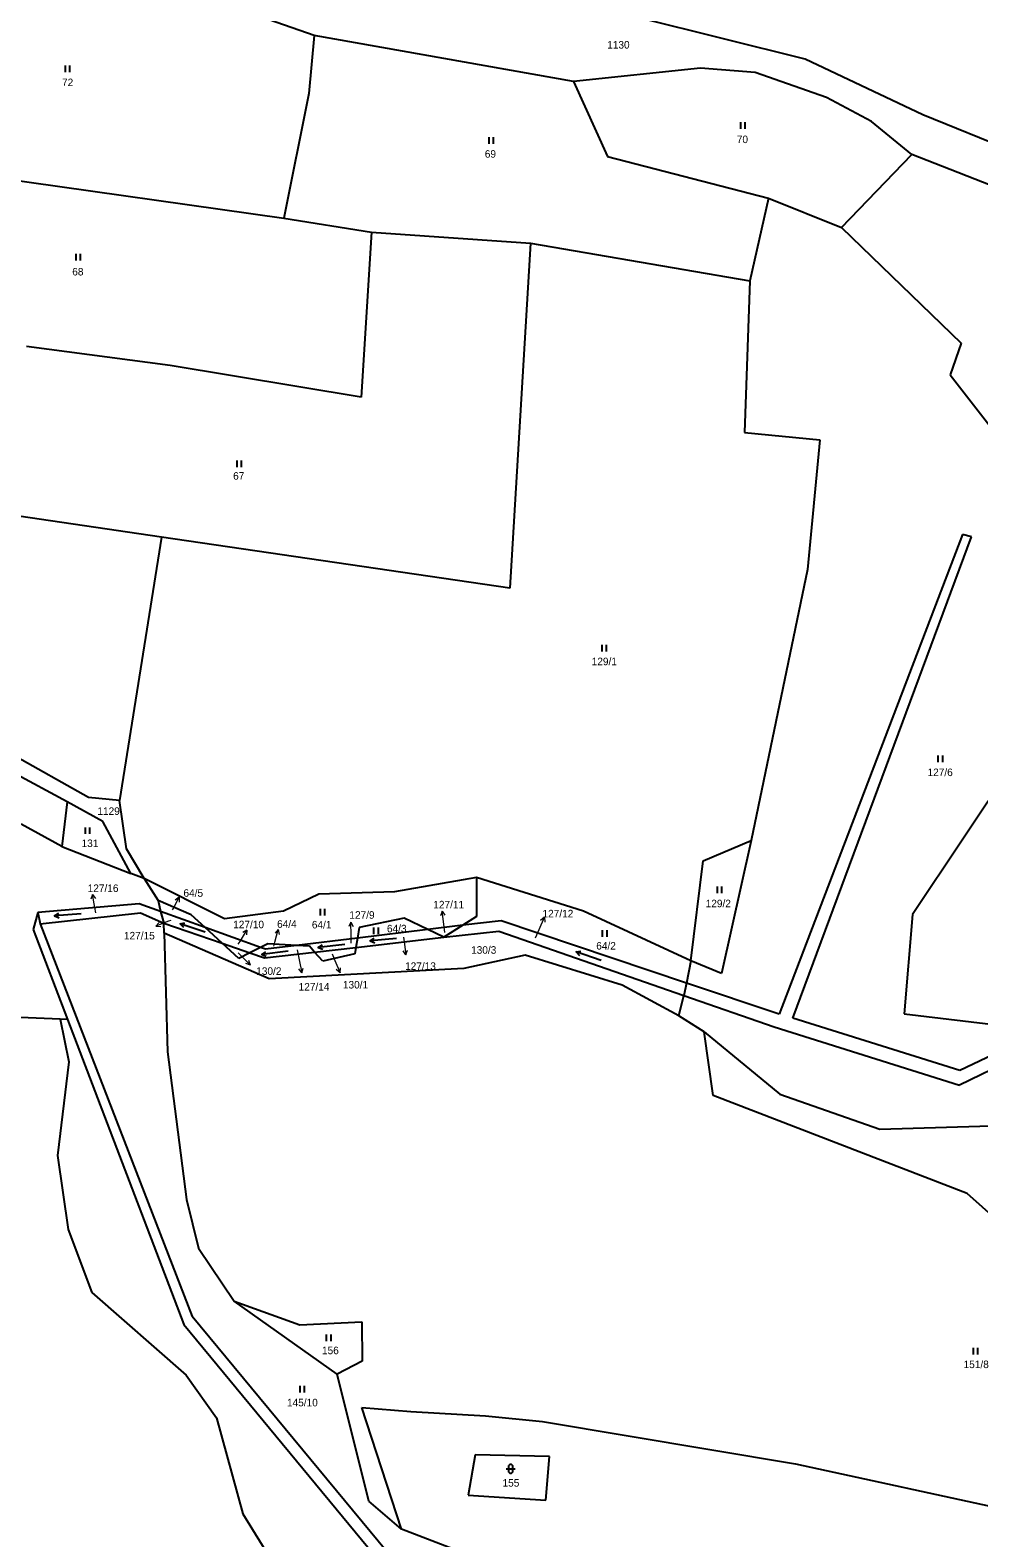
# Model space of a CAD drawing. Extents: x -765428 to -762163, y -1107632 to -1104975.
# Drawn here: x -763790.9 to -763576.9, y -1106368.4 to -1106028 of the extents above; entities that cross this region are included whole.
import ezdxf
from ezdxf.enums import TextEntityAlignment as Align

# ---------------------------------------------------------------- set-up
doc = ezdxf.new("R2010")
doc.units = 0
doc.header["$LTSCALE"] = 0.68
for name, color, linetype, lineweight in [('1', 7, 'Continuous', 25), ('3', 7, 'Continuous', 25), ('7', 7, 'Continuous', 13)]:
    doc.layers.add(name, color=color, linetype=linetype, lineweight=lineweight)
doc.layers.add('2', color=7, linetype='Continuous')

msp = doc.modelspace()

# ---------------------------------------------------------------- linework, layer by layer
at = {"layer": '1'}
for p, q in [((-763726.87, -1106029.18), (-763753.11, -1106020.03)), ((-763616.09, -1106034.57), (-763653.49, -1106025.2)), ((-763726.87, -1106029.18), (-763728.05, -1106042.27)), ((-763668.33, -1106039.62), (-763726.87, -1106029.18)), ((-763589.52, -1106047.15), (-763616.09, -1106034.57)), ((-763639.64, -1106036.55), (-763668.33, -1106039.62)), ((-763627.35, -1106037.56), (-763639.64, -1106036.55)), ((-763728.05, -1106042.27), (-763733.72, -1106070.47)), ((-763668.33, -1106039.62), (-763660.67, -1106056.49)), ((-763591.96, -1106056.09), (-763601.08, -1106048.6)), ((-763545.6, -1106064.87), (-763589.52, -1106047.15)), ((-763834.64, -1106056.18), (-763733.72, -1106070.47)), ((-763660.67, -1106056.49), (-763624.36, -1106065.9)), ((-763607.85, -1106072.56), (-763591.96, -1106056.09)), ((-763549.32, -1106072.75), (-763591.96, -1106056.09)), ((-763624.36, -1106065.9), (-763628.51, -1106084.61)), ((-763624.36, -1106065.9), (-763607.85, -1106072.56)), ((-763733.72, -1106070.47), (-763713.95, -1106073.6)), ((-763607.85, -1106072.56), (-763580.88, -1106098.69)), ((-763713.95, -1106073.6), (-763716.25, -1106110.83)), ((-763713.95, -1106073.6), (-763678.06, -1106076.1)), ((-763678.06, -1106076.1), (-763682.69, -1106153.96)), ((-763678.06, -1106076.1), (-763628.51, -1106084.61)), ((-763628.51, -1106084.61), (-763629.74, -1106118.85)), ((-763759.32, -1106103.75), (-763791.79, -1106099.42)), ((-763580.88, -1106098.69), (-763583.36, -1106105.79)), ((-763716.25, -1106110.83), (-763759.32, -1106103.75)), ((-763583.36, -1106105.79), (-763547.96, -1106151.37)), ((-763629.74, -1106118.85), (-763612.77, -1106120.48)), ((-763612.77, -1106120.48), (-763615.53, -1106149.74)), ((-763761.3, -1106142.44), (-763824.95, -1106133.12)), ((-763761.3, -1106142.44), (-763770.75, -1106201.91)), ((-763682.69, -1106153.96), (-763761.3, -1106142.44)), ((-763580.59, -1106141.87), (-763621.93, -1106250.16)), ((-763618.82, -1106251.05), (-763578.52, -1106142.37)), ((-763578.52, -1106142.37), (-763580.59, -1106141.87)), ((-763615.53, -1106149.74), (-763628.26, -1106210.99)), ((-763562.87, -1106184.23), (-763591.84, -1106227.65)), ((-763777.77, -1106201.24), (-763795.19, -1106191.48)), ((-763782.6, -1106202.25), (-763794.88, -1106195.63)), ((-763782.6, -1106202.25), (-763783.83, -1106212.34)), ((-763774.57, -1106206.66), (-763782.6, -1106202.25)), ((-763783.83, -1106212.34), (-763792.97, -1106207.29)), ((-763768.23, -1106218.43), (-763774.57, -1106206.66)), ((-763783.83, -1106212.34), (-763768.23, -1106218.43)), ((-763639.08, -1106215.54), (-763628.26, -1106210.99)), ((-763628.26, -1106210.99), (-763634.96, -1106240.97)), ((-763765.2, -1106219.51), (-763769.18, -1106212.83)), ((-763641.86, -1106238.12), (-763639.08, -1106215.54)), ((-763765.2, -1106219.51), (-763768.23, -1106218.43)), ((-763690.22, -1106219.29), (-763708.71, -1106222.53)), ((-763690.22, -1106219.29), (-763690.22, -1106228.12)), ((-763666.11, -1106226.9), (-763690.22, -1106219.29)), ((-763747.07, -1106228.62), (-763765.2, -1106219.51)), ((-763765.2, -1106219.51), (-763762.02, -1106224.5)), ((-763708.71, -1106222.53), (-763725.8, -1106223.1)), ((-763494.88, -1106221.53), (-763581.17, -1106262.89)), ((-763766.35, -1106225.23), (-763789.24, -1106227.25)), ((-763761.54, -1106226.97), (-763766.35, -1106225.23)), ((-763762.02, -1106224.5), (-763761.54, -1106226.97)), ((-763754.58, -1106227.73), (-763762.02, -1106224.5)), ((-763725.8, -1106223.1), (-763733.79, -1106226.89)), ((-763493.63, -1106223.59), (-763581.23, -1106266.21)), ((-763789.24, -1106227.25), (-763790.27, -1106231.05)), ((-763789.24, -1106227.25), (-763788.71, -1106229.75)), ((-763788.71, -1106229.75), (-763766.07, -1106227.27)), ((-763766.07, -1106227.27), (-763760.75, -1106229.63)), ((-763761.54, -1106226.97), (-763760.75, -1106229.63)), ((-763751.45, -1106230.61), (-763761.54, -1106226.97)), ((-763733.79, -1106226.89), (-763747.07, -1106228.62)), ((-763706.58, -1106228.48), (-763716.72, -1106230.63)), ((-763701.24, -1106231.04), (-763706.58, -1106228.48)), ((-763690.22, -1106228.12), (-763693.34, -1106230.1)), ((-763684.65, -1106229.06), (-763693.34, -1106230.1)), ((-763642.8, -1106243.14), (-763684.65, -1106229.06)), ((-763641.86, -1106238.12), (-763666.11, -1106226.9)), ((-763591.84, -1106227.65), (-763593.73, -1106250.12)), ((-763790.27, -1106231.05), (-763782.54, -1106251.34)), ((-763788.71, -1106229.75), (-763754.39, -1106318.42)), ((-763760.75, -1106229.63), (-763747.58, -1106234.17)), ((-763760.67, -1106231.87), (-763760.75, -1106229.63)), ((-763737.04, -1106242.16), (-763760.67, -1106231.87)), ((-763760.67, -1106231.87), (-763759.98, -1106258.64)), ((-763738.93, -1106235.13), (-763751.45, -1106230.61)), ((-763717.42, -1106235.09), (-763697.63, -1106232.82)), ((-763716.72, -1106230.63), (-763717.09, -1106233)), ((-763701.24, -1106231.04), (-763717.09, -1106233)), ((-763693.34, -1106230.1), (-763701.24, -1106231.04)), ((-763697.63, -1106232.82), (-763701.24, -1106231.04)), ((-763693.34, -1106230.1), (-763697.63, -1106232.82)), ((-763697.63, -1106232.82), (-763685.22, -1106231.4)), ((-763685.22, -1106231.4), (-763643.41, -1106245.93)), ((-763747.58, -1106234.17), (-763741.34, -1106236.32)), ((-763743.88, -1106237.58), (-763747.58, -1106234.17)), ((-763741.34, -1106236.32), (-763743.88, -1106237.58)), ((-763738.93, -1106235.13), (-763741.34, -1106236.32)), ((-763741.34, -1106236.32), (-763738.07, -1106237.45)), ((-763737.28, -1106234.32), (-763738.93, -1106235.13)), ((-763737.83, -1106235.53), (-763738.93, -1106235.13)), ((-763738.07, -1106237.45), (-763726.76, -1106236.16)), ((-763730.87, -1106234.68), (-763737.83, -1106235.53)), ((-763730.87, -1106234.68), (-763737.28, -1106234.32)), ((-763717.09, -1106233), (-763730.87, -1106234.68)), ((-763727.92, -1106234.85), (-763730.87, -1106234.68)), ((-763726.76, -1106236.16), (-763727.92, -1106234.85)), ((-763726.76, -1106236.16), (-763717.42, -1106235.09)), ((-763724.91, -1106238.23), (-763726.76, -1106236.16)), ((-763717.42, -1106235.09), (-763717.66, -1106236.58)), ((-763717.09, -1106233), (-763717.42, -1106235.09)), ((-763717.66, -1106236.58), (-763724.91, -1106238.23)), ((-763679.21, -1106236.82), (-763693.09, -1106239.89)), ((-763657.34, -1106243.6), (-763679.21, -1106236.82)), ((-763641.86, -1106238.12), (-763642.8, -1106243.14)), ((-763634.96, -1106240.97), (-763641.86, -1106238.12)), ((-763693.09, -1106239.89), (-763737.04, -1106242.16)), ((-763642.8, -1106243.14), (-763643.41, -1106245.93)), ((-763621.93, -1106250.16), (-763642.8, -1106243.14)), ((-763644.59, -1106250.54), (-763657.34, -1106243.6)), ((-763644.59, -1106250.54), (-763643.41, -1106245.93)), ((-763643.41, -1106245.93), (-763623.02, -1106253.02)), ((-763784.17, -1106251.28), (-763800.14, -1106250.66)), ((-763782.54, -1106251.34), (-763784.17, -1106251.28)), ((-763784.17, -1106251.28), (-763782.2, -1106260.97)), ((-763782.54, -1106251.34), (-763756.3, -1106320.24)), ((-763638.88, -1106254.14), (-763644.59, -1106250.54)), ((-763623.02, -1106253.02), (-763581.23, -1106266.21)), ((-763581.17, -1106262.89), (-763618.82, -1106251.05)), ((-763636.82, -1106268.57), (-763638.88, -1106254.14)), ((-763638.88, -1106254.14), (-763621.75, -1106268.24)), ((-763759.98, -1106258.64), (-763755.68, -1106292)), ((-763782.2, -1106260.97), (-763784.81, -1106282.1)), ((-763579.48, -1106290.69), (-763636.82, -1106268.57)), ((-763621.75, -1106268.24), (-763599.23, -1106276.16)), ((-763599.23, -1106276.16), (-763490.85, -1106272.72)), ((-763784.81, -1106282.1), (-763782.33, -1106298.82)), ((-763565.74, -1106303.01), (-763579.48, -1106290.69)), ((-763755.68, -1106292), (-763752.97, -1106303.03)), ((-763782.33, -1106298.82), (-763777, -1106313)), ((-763752.97, -1106303.03), (-763744.87, -1106314.96)), ((-763777, -1106313), (-763755.76, -1106331.69)), ((-763721.66, -1106331.42), (-763744.87, -1106314.96)), ((-763744.87, -1106314.96), (-763730.08, -1106320.34)), ((-763756.3, -1106320.24), (-763682.16, -1106409.87)), ((-763679.72, -1106408.64), (-763754.39, -1106318.42)), ((-763730.08, -1106320.34), (-763716.12, -1106319.61)), ((-763716.12, -1106319.61), (-763716.01, -1106328.54)), ((-763755.76, -1106331.69), (-763748.92, -1106341.3)), ((-763716.01, -1106328.54), (-763721.66, -1106331.42)), ((-763714.5, -1106360.14), (-763721.66, -1106331.42)), ((-763748.92, -1106341.3), (-763742.98, -1106362.99)), ((-763716.07, -1106338.97), (-763705.01, -1106339.85)), ((-763707.15, -1106366.45), (-763716.07, -1106338.97)), ((-763705.01, -1106339.85), (-763688.18, -1106340.89)), ((-763688.18, -1106340.89), (-763675.35, -1106342.14)), ((-763675.35, -1106342.14), (-763618.27, -1106351.7)), ((-763690.53, -1106349.66), (-763692.07, -1106358.76)), ((-763673.76, -1106350.02), (-763690.53, -1106349.66)), ((-763674.55, -1106359.9), (-763673.76, -1106350.02)), ((-763618.27, -1106351.7), (-763461.07, -1106385.99)), ((-763692.07, -1106358.76), (-763674.55, -1106359.9)), ((-763707.15, -1106366.45), (-763714.5, -1106360.14)), ((-763742.98, -1106362.99), (-763732.72, -1106379.58)), ((-763692.46, -1106372.08), (-763707.15, -1106366.45))]:
    msp.add_line(p, q, dxfattribs=at)
for points in [[(-763601.08, -1106048.6), (-763611.28, -1106043.21), (-763627.35, -1106037.56)], [(-763769.18, -1106212.83), (-763770.75, -1106201.91), (-763777.77, -1106201.24)], [(-763747.58, -1106234.17), (-763751.45, -1106230.61), (-763754.58, -1106227.73)], [(-763593.73, -1106250.12), (-763570.42, -1106252.88), (-763566.7, -1106234.64)]]:
    msp.add_lwpolyline(points, dxfattribs=at)
at = {"layer": '3'}
for p, q in [((-763783.001, -1106037.51), (-763783.001, -1106036.01)), ((-763782, -1106037.51), (-763782, -1106036.01)), ((-763630.581, -1106050.27), (-763630.581, -1106048.77)), ((-763629.58, -1106050.27), (-763629.58, -1106048.77)), ((-763687.401, -1106053.67), (-763687.401, -1106052.17)), ((-763686.4, -1106053.67), (-763686.4, -1106052.17)), ((-763780.581, -1106080.03), (-763780.581, -1106078.53)), ((-763779.58, -1106080.03), (-763779.58, -1106078.53)), ((-763744.261, -1106126.64), (-763744.261, -1106125.14)), ((-763743.26, -1106126.64), (-763743.26, -1106125.14)), ((-763661.891, -1106168.26), (-763661.891, -1106166.76)), ((-763660.89, -1106168.26), (-763660.89, -1106166.76)), ((-763586.021, -1106193.3), (-763586.021, -1106191.8)), ((-763585.02, -1106193.3), (-763585.02, -1106191.8)), ((-763778.451, -1106209.49), (-763778.451, -1106207.99)), ((-763777.45, -1106209.49), (-763777.45, -1106207.99)), ((-763635.851, -1106222.82), (-763635.851, -1106221.32)), ((-763634.85, -1106222.82), (-763634.85, -1106221.32)), ((-763785.44, -1106227.952), (-763784.501, -1106227.384)), ((-763725.451, -1106227.91), (-763725.451, -1106226.41)), ((-763724.45, -1106227.91), (-763724.45, -1106226.41)), ((-763757.1, -1106229.74), (-763756.013, -1106229.584)), ((-763713.361, -1106232.08), (-763713.361, -1106230.58)), ((-763712.36, -1106232.08), (-763712.36, -1106230.58)), ((-763661.761, -1106232.73), (-763661.761, -1106231.23)), ((-763660.76, -1106232.73), (-763660.76, -1106231.23)), ((-763738.686, -1106236.709), (-763737.777, -1106236.092)), ((-763725.922, -1106235.097), (-763725.002, -1106234.496)), ((-763714.216, -1106233.624), (-763713.287, -1106233.04)), ((-763667.77, -1106236.1), (-763666.683, -1106235.944)), ((-763724.051, -1106323.99), (-763724.051, -1106322.49)), ((-763723.05, -1106323.99), (-763723.05, -1106322.49)), ((-763578.071, -1106326.98), (-763578.071, -1106325.48)), ((-763577.07, -1106326.98), (-763577.07, -1106325.48)), ((-763730.021, -1106335.59), (-763730.021, -1106334.09)), ((-763729.02, -1106335.59), (-763729.02, -1106334.09)), ((-763683.511, -1106352.831), (-763681.509, -1106352.831)), ((-763683.011, -1106352.331), (-763683.011, -1106353.332)), ((-763682.009, -1106353.332), (-763682.009, -1106352.331))]:
    msp.add_line(p, q, dxfattribs=at)
for points in [[(-763779.455, -1106227.533), (-763785.44, -1106227.952), (-763784.431, -1106228.384)], [(-763751.427, -1106231.693), (-763757.1, -1106229.74), (-763756.339, -1106230.532)], [(-763732.73, -1106235.978), (-763738.686, -1106236.709), (-763737.655, -1106237.088)], [(-763719.954, -1106234.47), (-763725.922, -1106235.097), (-763724.897, -1106235.493)], [(-763708.239, -1106233.101), (-763714.216, -1106233.624), (-763713.199, -1106234.039)], [(-763662.097, -1106238.053), (-763667.77, -1106236.1), (-763667.009, -1106236.892)]]:
    msp.add_lwpolyline(points, dxfattribs=at)
for centre, start, end in [((-763682.51, -1106352.3309), 0, 180), ((-763682.51, -1106353.3309), 180, 359.98789)]:
    msp.add_arc(centre, 0.5, start, end, dxfattribs=at)
at = {"layer": '7'}
for p, q in [((-763776.901, -1106223.145), (-763777.22, -1106224.218)), ((-763757.338, -1106223.736), (-763758.238, -1106224.401)), ((-763718.562, -1106229.389), (-763719.046, -1106230.4)), ((-763697.976, -1106226.891), (-763698.351, -1106227.946)), ((-763674.907, -1106228.288), (-763675.76, -1106229.014)), ((-763762.552, -1106230.285), (-763761.437, -1106230.394)), ((-763742.034, -1106231.168), (-763742.979, -1106231.768)), ((-763734.943, -1106231.051), (-763735.686, -1106231.889)), ((-763706.162, -1106236.802), (-763705.806, -1106235.74)), ((-763741.208, -1106239.122), (-763741.562, -1106238.06)), ((-763729.647, -1106240.826), (-763729.347, -1106239.747)), ((-763721.007, -1106240.822), (-763720.938, -1106239.705))]:
    msp.add_line(p, q, dxfattribs=at)
for points in [[(-763776.16, -1106227.28), (-763776.38, -1106226.1), (-763776.901, -1106223.145), (-763776.234, -1106224.044)], [(-763758.82, -1106226.64), (-763758.7, -1106226.41), (-763757.338, -1106223.736), (-763757.346, -1106224.856)], [(-763759.17, -1106228.99), (-763759.75, -1106229.21), (-763762.552, -1106230.285), (-763761.796, -1106229.459)], [(-763718.49, -1106234.14), (-763718.51, -1106232.39), (-763718.562, -1106229.389), (-763718.044, -1106230.382)], [(-763697.37, -1106231.71), (-763697.61, -1106229.87), (-763697.976, -1106226.891), (-763697.357, -1106227.824)], [(-763676.88, -1106232.96), (-763676.08, -1106231.05), (-763674.907, -1106228.288), (-763674.838, -1106229.405)], [(-763743.97, -1106234.39), (-763743.58, -1106233.74), (-763742.034, -1106231.168), (-763742.121, -1106232.284)], [(-763735.96, -1106234.84), (-763735.72, -1106233.95), (-763734.943, -1106231.051), (-763734.719, -1106232.148)], [(-763706.72, -1106232.78), (-763706.58, -1106233.83), (-763706.162, -1106236.802), (-763706.798, -1106235.88)], [(-763744.04, -1106236.3), (-763743.33, -1106237), (-763741.208, -1106239.122), (-763742.27, -1106238.768)], [(-763730.67, -1106235.67), (-763730.22, -1106237.88), (-763729.647, -1106240.826), (-763730.33, -1106239.938)], [(-763722.82, -1106236.54), (-763722.18, -1106238.06), (-763721.007, -1106240.822), (-763721.86, -1106240.096)]]:
    msp.add_lwpolyline(points, dxfattribs=at)

# ---------------------------------------------------------------- texts
at = {"layer": '2'}
for s, p in [('1130', (-763660.73, -1106032.155)), ('1129', (-763775.77, -1106205.185)), ('131', (-763779.34, -1106212.435)), ('64/5', (-763756.35, -1106223.665)), ('127/10', (-763745.13, -1106230.775)), ('64/4', (-763735.22, -1106230.665)), ('127/12', (-763675.33, -1106228.315)), ('130/2', (-763739.93, -1106241.295)), ('127/13', (-763706.34, -1106240.175)), ('127/14', (-763730.36, -1106244.835)), ('130/1', (-763720.37, -1106244.375)), ('156', (-763725.09, -1106326.945)), ('155', (-763684.35, -1106356.845))]:
    msp.add_text(s, height=1.7, dxfattribs=at).set_placement(p)
for s, p in [('72', (-763782.489, -1106040.635)), ('70', (-763630.219, -1106053.505)), ('69', (-763687.089, -1106056.795)), ('68', (-763780.179, -1106083.385)), ('67', (-763743.879, -1106129.495)), ('129/1', (-763661.38, -1106171.385)), ('127/6', (-763585.6, -1106196.415)), ('129/2', (-763635.66, -1106226.035)), ('64/1', (-763725.159, -1106230.815)), ('64/3', (-763708.219, -1106231.695)), ('130/3', (-763688.6, -1106236.525)), ('64/2', (-763660.989, -1106235.585)), ('151/8', (-763577.46, -1106330.085)), ('145/10', (-763729.51, -1106338.715))]:
    msp.add_text(s, height=1.7, dxfattribs=at).set_placement(p, align=Align.CENTER)
for s, p in [('127/16', (-763771.009, -1106222.585)), ('127/11', (-763693.019, -1106226.285)), ('127/9', (-763713.22, -1106228.625)), ('127/15', (-763762.829, -1106233.295))]:
    msp.add_text(s, height=1.7, dxfattribs=at).set_placement(p, align=Align.RIGHT)

doc.saveas('drawing.dxf')
